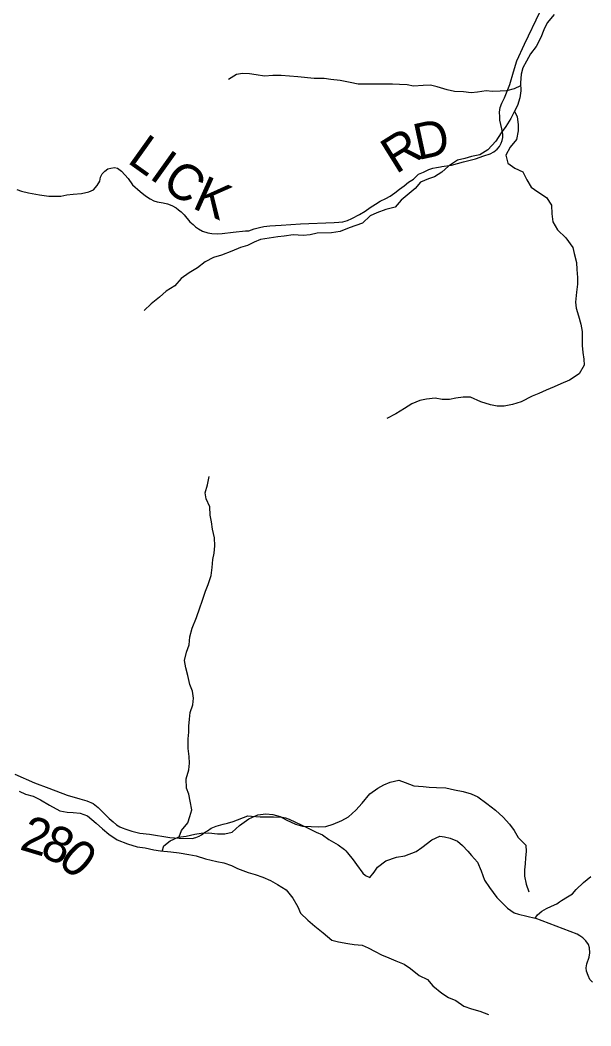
# Model space of a CAD drawing. Extents: x 0 to 34, y 0 to 22.
# Drawn here: x 2.975 to 3.875, y 14.962 to 16.547 of the extents above; entities that cross this region are included whole.
import ezdxf

# ---------------------------------------------------------------- set-up
doc = ezdxf.new("R2010")
doc.units = 0
for name, color, linetype in [('GM_X_County_Text', 7, 'Continuous'), ('GM_X_Minor_River', 7, 'Continuous'), ('GM_X_Township_Road', 7, 'Continuous'), ('GM_X_Township_Road_Text', 7, 'Continuous')]:
    doc.layers.add(name, color=color, linetype=linetype)

msp = doc.modelspace()

# ---------------------------------------------------------------- linework, layer by layer
at = {"layer": 'GM_X_Minor_River'}
for points in [[(3.817, 16.5559), (3.8059, 16.5427), (3.8006, 16.5318), (3.7956, 16.5197), (3.7883, 16.5057), (3.7795, 16.494), (3.773, 16.4826), (3.7673, 16.472), (3.7646, 16.4622), (3.7637, 16.4482), (3.764, 16.4356), (3.7625, 16.4247), (3.759, 16.4125), (3.754, 16.4027), (3.7483, 16.3921), (3.7406, 16.3793), (3.7334, 16.3695), (3.725, 16.3566), (3.712, 16.3427), (3.6999, 16.3348), (3.6866, 16.3322), (3.676, 16.3288), (3.6643, 16.3263), (3.6503, 16.3169), (3.6396, 16.3074), (3.6282, 16.3003), (3.6187, 16.297), (3.6062, 16.2917), (3.5978, 16.2815), (3.5883, 16.274), (3.5758, 16.2631), (3.5663, 16.2525), (3.5515, 16.2484), (3.5375, 16.2436), (3.5269, 16.2387), (3.5147, 16.227), (3.4935, 16.2196), (3.4798, 16.214), (3.4658, 16.2118), (3.4435, 16.2112), (3.4325, 16.2086), (3.4212, 16.2075), (3.4057, 16.2087), (3.3913, 16.2065), (3.3811, 16.2058), (3.3678, 16.2036), (3.3542, 16.2011), (3.344, 16.197), (3.3333, 16.1921), (3.3224, 16.1888), (3.3091, 16.1831), (3.2928, 16.1768), (3.2799, 16.1731), (3.267, 16.166), (3.2545, 16.1569), (3.2416, 16.1487), (3.229, 16.14), (3.2191, 16.1283), (3.2051, 16.1197), (3.1948, 16.1106), (3.1815, 16.1001), (3.1709, 16.0895)], [(3.7639, 16.4436), (3.7535, 16.4387), (3.7417, 16.4358), (3.7319, 16.4351), (3.7194, 16.4348), (3.7096, 16.4356), (3.696, 16.4338), (3.6858, 16.4323), (3.6737, 16.4339), (3.6597, 16.4348), (3.648, 16.4375), (3.6325, 16.4421), (3.6219, 16.4445), (3.6106, 16.4442), (3.5951, 16.4431), (3.5849, 16.4451), (3.5731, 16.4459), (3.5622, 16.4464), (3.5512, 16.4464), (3.5391, 16.4461), (3.5081, 16.4463), (3.4953, 16.449), (3.4798, 16.4518), (3.4647, 16.4534), (3.4545, 16.4553), (3.4386, 16.4551), (3.4129, 16.4575), (3.3997, 16.4587), (3.3868, 16.4599), (3.3732, 16.46), (3.3603, 16.4586), (3.3471, 16.4609), (3.3365, 16.4625), (3.3259, 16.463), (3.3161, 16.4615), (3.3036, 16.4536)], [(3.7543, 16.4033), (3.7585, 16.3951), (3.7603, 16.3822), (3.7603, 16.3727), (3.7575, 16.3591), (3.7472, 16.347), (3.7404, 16.3341), (3.7437, 16.3216), (3.7546, 16.3136), (3.7674, 16.3078), (3.7738, 16.2953), (3.7805, 16.2838), (3.7911, 16.2766), (3.8046, 16.2674), (3.8125, 16.2556), (3.8132, 16.2419), (3.8146, 16.229), (3.8221, 16.2168), (3.8349, 16.2042), (3.8461, 16.1886), (3.8483, 16.1791), (3.852, 16.1651), (3.8527, 16.1541), (3.8534, 16.1415), (3.8533, 16.1309), (3.8521, 16.1184), (3.8505, 16.1025), (3.8512, 16.093), (3.8549, 16.0812), (3.859, 16.0679), (3.8608, 16.0565), (3.8607, 16.0467), (3.861, 16.0342), (3.8621, 16.0232), (3.8636, 16.0129), (3.8639, 16.0034), (3.8562, 15.9894), (3.8407, 15.9797), (3.8274, 15.9737), (3.8168, 15.9692), (3.8043, 15.964), (3.7925, 15.9587), (3.7823, 15.9546), (3.7648, 15.9456), (3.7512, 15.9415), (3.7379, 15.9386), (3.727, 15.9386), (3.7164, 15.9406), (3.7013, 15.9452), (3.6847, 15.9529), (3.6734, 15.953), (3.6616, 15.9512), (3.6518, 15.9493), (3.6404, 15.949), (3.6295, 15.951), (3.6155, 15.9499), (3.6052, 15.9473), (3.5924, 15.9425), (3.581, 15.935), (3.5673, 15.9267), (3.5533, 15.9192)], [(3.2258, 15.2595), (3.2297, 15.2699), (3.2396, 15.2816), (3.2424, 15.2919), (3.2458, 15.3025), (3.2433, 15.3161), (3.2411, 15.3271), (3.2373, 15.3366), (3.237, 15.3511), (3.2413, 15.3655), (3.2421, 15.3757), (3.2414, 15.3863), (3.24, 15.3992), (3.2401, 15.414), (3.2409, 15.4246), (3.2413, 15.4341), (3.2422, 15.4455), (3.243, 15.4557), (3.2472, 15.4678), (3.2484, 15.4781), (3.247, 15.4894), (3.2429, 15.4997), (3.2396, 15.5141), (3.2362, 15.5259), (3.234, 15.5377), (3.2375, 15.5509), (3.2417, 15.5623), (3.2426, 15.5748), (3.2464, 15.5888), (3.2534, 15.6055), (3.2584, 15.6206), (3.2622, 15.6312), (3.2672, 15.6471), (3.2715, 15.6577), (3.2761, 15.6717), (3.2777, 15.6842), (3.2789, 15.6967), (3.2808, 15.7069), (3.282, 15.7183), (3.2817, 15.7312), (3.2784, 15.7449), (3.2766, 15.7563), (3.2748, 15.7669), (3.2741, 15.7802), (3.2685, 15.7924), (3.2667, 15.8022), (3.2705, 15.8147), (3.2729, 15.8276)], [(3.1989, 15.2373), (3.2016, 15.2455), (3.2115, 15.2534), (3.2244, 15.2594), (3.2369, 15.2608), (3.2505, 15.2638), (3.2607, 15.2656), (3.2728, 15.2663), (3.2861, 15.2647), (3.2978, 15.2646), (3.3095, 15.2672), (3.3209, 15.2777), (3.3354, 15.2883), (3.3498, 15.2943), (3.3626, 15.2961), (3.3732, 15.2949), (3.3849, 15.2918), (3.3947, 15.2864), (3.4094, 15.2795), (3.42, 15.2768), (3.4336, 15.2759), (3.4457, 15.2755), (3.457, 15.2758), (3.4684, 15.2795), (3.4824, 15.2855), (3.4927, 15.2915), (3.5041, 15.3017), (3.514, 15.313), (3.5262, 15.3273), (3.5387, 15.3363), (3.5486, 15.3416), (3.5581, 15.3461), (3.5721, 15.349), (3.5819, 15.3456), (3.5958, 15.3402), (3.6102, 15.3389), (3.62, 15.3381), (3.6314, 15.3377), (3.6461, 15.3372), (3.6597, 15.3337), (3.6733, 15.331), (3.6861, 15.3275), (3.6967, 15.3229), (3.7106, 15.3125), (3.7242, 15.3018), (3.7362, 15.2908), (3.7464, 15.2797), (3.7535, 15.2698), (3.7598, 15.2588), (3.7722, 15.2466), (3.7729, 15.2367), (3.7717, 15.2268), (3.7709, 15.217), (3.7701, 15.2075), (3.7701, 15.1976), (3.7726, 15.1851), (3.7767, 15.173)], [(2.9737, 15.3318), (2.9835, 15.3268), (2.9956, 15.3237), (3.0073, 15.3179), (3.0216, 15.3099), (3.0378, 15.3007), (3.0492, 15.2987), (3.059, 15.2979), (3.0699, 15.2971), (3.0816, 15.2928), (3.0948, 15.2814), (3.105, 15.2722), (3.1151, 15.2642), (3.1279, 15.255), (3.1445, 15.2485), (3.1596, 15.2442), (3.1725, 15.2422), (3.1861, 15.2395), (3.1966, 15.2375), (3.2129, 15.2359), (3.2261, 15.2347), (3.2412, 15.2319), (3.2526, 15.2296), (3.2673, 15.225), (3.2854, 15.2211), (3.2964, 15.2187), (3.3081, 15.2145), (3.3179, 15.2099), (3.3345, 15.2033), (3.3454, 15.2002), (3.3575, 15.1963), (3.3699, 15.191), (3.3809, 15.1848), (3.3944, 15.1764), (3.4049, 15.1631), (3.4128, 15.1494), (3.4169, 15.1395), (3.4285, 15.1284), (3.4398, 15.1189), (3.4526, 15.1082), (3.4662, 15.0971), (3.4771, 15.094), (3.4915, 15.0916), (3.5017, 15.09), (3.5141, 15.0888), (3.5239, 15.0846), (3.5349, 15.0792), (3.5447, 15.0735), (3.556, 15.0692), (3.5673, 15.0642), (3.5805, 15.0592), (3.5903, 15.0523), (3.6038, 15.0413), (3.617, 15.0347), (3.6257, 15.0248), (3.6396, 15.0133), (3.6505, 15.0065), (3.6618, 15.0018), (3.6743, 14.9927), (3.6867, 14.9884), (3.6995, 14.9849), (3.7131, 14.9795)]]:
    msp.add_lwpolyline(points, dxfattribs=at)
at = {"layer": 'GM_X_Township_Road'}
for points in [[(3.6397, 16.3162), (3.6551, 16.3184), (3.674, 16.3237), (3.6926, 16.3287), (3.7058, 16.3331), (3.7159, 16.3364), (3.7219, 16.3394), (3.7272, 16.3438), (3.7307, 16.3482), (3.7332, 16.353), (3.7349, 16.3576), (3.736, 16.3622), (3.7358, 16.3674), (3.7345, 16.3756), (3.7314, 16.3892), (3.7309, 16.3946), (3.7304, 16.4022), (3.7316, 16.4095), (3.7343, 16.4162), (3.7385, 16.4244), (3.7468, 16.4457), (3.7529, 16.4656), (3.7579, 16.4828), (3.7699, 16.5092), (3.7946, 16.5607)], [(2.9703, 16.2799), (2.9776, 16.2776), (2.9885, 16.2751), (3.0059, 16.2715), (3.0205, 16.2699), (3.0304, 16.2694), (3.0394, 16.2699), (3.0488, 16.2715), (3.0588, 16.2728), (3.0718, 16.2736), (3.0835, 16.2763), (3.0911, 16.2795), (3.0965, 16.2864), (3.1006, 16.2933), (3.102, 16.2994), (3.1045, 16.3048), (3.1085, 16.3092), (3.1133, 16.3126), (3.1183, 16.314), (3.1237, 16.3147), (3.1286, 16.3138), (3.135, 16.309), (3.1453, 16.2973), (3.1522, 16.2874), (3.1644, 16.277), (3.1727, 16.2701), (3.1803, 16.2655), (3.1857, 16.2625), (3.1914, 16.2606), (3.2006, 16.259), (3.2073, 16.2575), (3.2142, 16.2548), (3.2209, 16.2512), (3.2249, 16.2483), (3.2291, 16.2449), (3.2339, 16.2401), (3.2429, 16.2294), (3.2477, 16.225), (3.2484, 16.2244)], [(3.2484, 16.2244), (3.2517, 16.2211), (3.2561, 16.2181), (3.2626, 16.2146), (3.2709, 16.2119), (3.2772, 16.2108), (3.2856, 16.2104), (3.2938, 16.211), (3.3109, 16.2129), (3.3306, 16.215), (3.3354, 16.215), (3.3438, 16.2179), (3.3526, 16.2204), (3.3593, 16.2221), (3.3689, 16.2229), (3.3865, 16.2238), (3.4171, 16.2259), (3.4703, 16.2284), (3.4772, 16.2286), (3.4839, 16.2294), (3.491, 16.2315), (3.4981, 16.2343), (3.51, 16.2405), (3.5188, 16.2458), (3.527, 16.2518), (3.535, 16.2569), (3.5427, 16.2616), (3.5515, 16.2661), (3.5586, 16.2699), (3.5655, 16.2747), (3.5731, 16.2805), (3.5802, 16.2862), (3.5871, 16.2918), (3.5953, 16.2962), (3.6031, 16.3041), (3.6108, 16.3077), (3.6193, 16.3117), (3.6254, 16.3138), (3.6315, 16.3147), (3.6378, 16.3159), (3.6397, 16.3162)], [(2.9668, 15.3585), (2.9981, 15.3448), (3.0203, 15.3365), (3.0492, 15.3252), (3.0694, 15.3197), (3.0806, 15.3165), (3.0901, 15.3124), (3.0981, 15.3058), (3.1036, 15.3005), (3.1103, 15.2938), (3.1157, 15.2886), (3.1216, 15.2833), (3.1269, 15.2789), (3.1325, 15.2756), (3.1362, 15.2738), (3.1418, 15.2718), (3.1515, 15.2686), (3.1638, 15.2657), (3.179, 15.2639), (3.2109, 15.2587), (3.2259, 15.2579), (3.2463, 15.257), (3.252, 15.2585), (3.2576, 15.2607), (3.2611, 15.2627), (3.2659, 15.2665), (3.2704, 15.2694), (3.2762, 15.2732), (3.2843, 15.2768), (3.2954, 15.2795), (3.3019, 15.2813), (3.3112, 15.2839), (3.3342, 15.2928), (3.3397, 15.2922), (3.3466, 15.2918), (3.3537, 15.2912), (3.3638, 15.2914), (3.3743, 15.2912), (3.3884, 15.2906), (3.3935, 15.2896), (3.3993, 15.2876), (3.428, 15.2738), (3.4418, 15.2671), (3.4519, 15.2627), (3.4616, 15.2556), (3.4763, 15.2471), (3.4863, 15.2399), (3.4885, 15.2377)], [(3.4885, 15.2377), (3.4913, 15.2348), (3.4998, 15.2235), (3.5053, 15.2161), (3.5152, 15.2027), (3.5196, 15.1988), (3.5265, 15.1958), (3.5329, 15.2039), (3.5382, 15.2118), (3.5515, 15.2219), (3.5681, 15.2276), (3.5817, 15.2296), (3.5995, 15.2366), (3.6081, 15.2431), (3.6239, 15.2552), (3.6368, 15.2609), (3.6439, 15.2597), (3.653, 15.2576), (3.6645, 15.253), (3.6721, 15.2463), (3.6805, 15.2372), (3.6866, 15.2302), (3.6961, 15.2196), (3.7015, 15.2061), (3.7072, 15.1913), (3.7149, 15.18), (3.7264, 15.1641), (3.7383, 15.1519), (3.743, 15.1471), (3.7537, 15.14), (3.7608, 15.1376), (3.7868, 15.1317)], [(3.7868, 15.1317), (3.7907, 15.1366), (3.7971, 15.1424), (3.8046, 15.1469), (3.8125, 15.1505), (3.821, 15.1544), (3.825, 15.1572), (3.8281, 15.1596), (3.8376, 15.1653), (3.8455, 15.1701), (3.8515, 15.1768), (3.8628, 15.1879), (3.8748, 15.1974)], [(3.8774, 15.0308), (3.8732, 15.0351), (3.8703, 15.041), (3.8679, 15.0478), (3.8671, 15.0535), (3.8683, 15.0598), (3.8717, 15.0701), (3.8731, 15.0771), (3.8725, 15.0848), (3.8707, 15.0901), (3.8669, 15.0957), (3.8622, 15.1008), (3.8572, 15.1036), (3.8529, 15.1062), (3.8087, 15.1232), (3.7868, 15.1317)]]:
    msp.add_lwpolyline(points, dxfattribs=at)

# ---------------------------------------------------------------- texts
at = {"layer": 'GM_X_County_Text'}
msp.add_text('SCIOTO COUNTY', height=0.189394, rotation=23.8999, dxfattribs=at).set_placement((2.8904, 14.2774))
at = {"layer": 'GM_X_Township_Road_Text'}
for s, rotation, p in [('D', 12.1894, (3.6022, 16.3264)), ('L', 324.5136, (3.1424, 16.3236)), ('R', 31.9123, (3.5674, 16.3037)), ('I', 324.4932, (3.177, 16.2989)), ('C', 323.963, (3.1958, 16.2855)), ('K', 335.8868, (3.2447, 16.2515)), ('2', 343.2389, (2.9727, 15.2404)), ('8', 335.1387, (3.0043, 15.231)), ('0', 319.3369, (3.0325, 15.2185))]:
    msp.add_text(s, height=0.0568, rotation=rotation, dxfattribs=at).set_placement(p)

doc.saveas('drawing.dxf')
